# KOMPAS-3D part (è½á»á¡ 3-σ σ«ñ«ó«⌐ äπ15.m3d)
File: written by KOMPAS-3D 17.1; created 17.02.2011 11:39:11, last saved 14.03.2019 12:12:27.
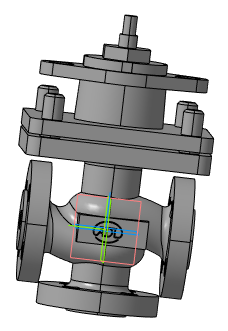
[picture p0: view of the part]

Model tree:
1. Плоскость XY
2. Плоскость ZX
3. Плоскость ZY
4. Ось X
5. Ось Y
6. Ось Z
7. Начало координат
8. Операция без истории:2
